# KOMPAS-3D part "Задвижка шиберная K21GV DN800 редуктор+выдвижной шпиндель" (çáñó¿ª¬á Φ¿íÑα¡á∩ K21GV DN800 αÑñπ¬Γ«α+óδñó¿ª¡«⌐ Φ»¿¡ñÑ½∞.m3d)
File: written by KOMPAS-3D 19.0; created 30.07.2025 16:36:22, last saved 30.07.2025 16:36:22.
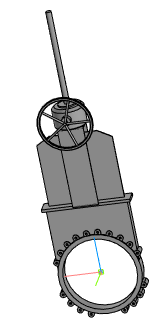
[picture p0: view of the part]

Document properties: Полное имя файла: Задвижка шиберная K21GV DN800 редуктор+выдвижной шпиндель.a3d

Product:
- Part/product: Задвижка шиберная K21GV DN800 редуктор+выдвижной шпиндель
    Масса: 801.169

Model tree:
1. Операция без истории:1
